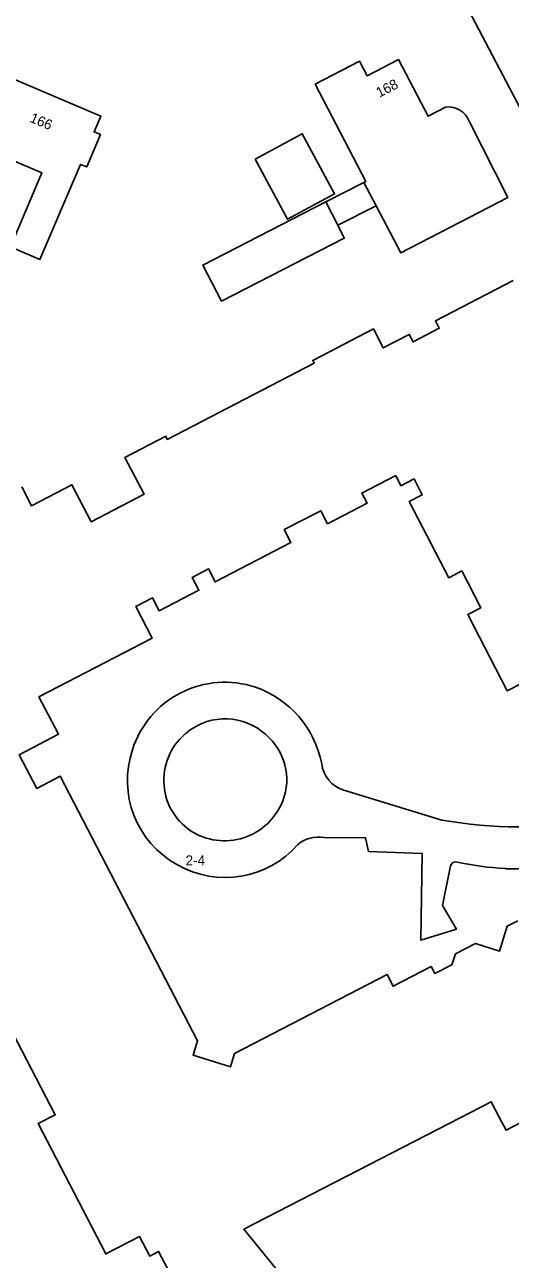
# Model space of a CAD drawing. Extents: x 162073 to 163043, y 381818 to 382561.
# Drawn here: x 162567.8 to 162616.1, y 382336.5 to 382459.4 of the extents above; entities that cross this region are included whole.
import ezdxf

# ---------------------------------------------------------------- set-up
doc = ezdxf.new("R2010")
doc.units = 0
for name, color, linetype in [('IMGEO_Erf', 7, 'Continuous'), ('IMGEO_Pand', 7, 'Continuous'), ('IMGEO_Pand_nummerreeks', 7, 'Continuous'), ('IMGEO_Rijbaan_lokaal_open', 7, 'Continuous')]:
    doc.layers.add(name, color=color, linetype=linetype)

msp = doc.modelspace()

# ---------------------------------------------------------------- linework, layer by layer
at = {"layer": 'IMGEO_Erf'}
for points in [[(162648.23, 382391.42), (162634.89, 382417.2), (162620.47, 382444.67), (162611.28, 382462.18)], [(162605.24, 382436.7), (162602.77, 382441.39), (162598.95, 382439.45), (162599.6, 382438.16), (162587.38, 382431.9), (162585.53, 382435.49), (162597.76, 382441.78), (162601.55, 382443.69), (162601.74, 382443.79), (162596.7, 382453.5), (162601.1, 382455.78), (162601.86, 382454.32), (162604.99, 382455.94), (162607.93, 382450.29), (162609.68, 382451.2)], [(162612.02, 382449.8), (162615.89, 382442.22), (162605.24, 382436.7)], [(162567.49, 382413.4), (162568.46, 382411.53), (162572.48, 382413.62), (162574.39, 382409.94), (162579.67, 382412.68), (162577.77, 382416.34), (162581.82, 382418.45), (162581.98, 382418.13), (162596.6, 382425.72), (162596.46, 382425.99), (162598.06, 382426.83), (162602.49, 382429.13), (162603.48, 382427.24), (162606.06, 382428.58), (162606.45, 382427.84), (162609.05, 382429.19), (162608.66, 382429.93), (162616.42, 382433.96)], [(162617.11, 382393.79), (162615.82, 382393.12), (162611.89, 382400.71), (162613.19, 382401.38), (162611.29, 382405.04), (162609.99, 382404.36), (162606.06, 382411.95), (162607.35, 382412.62), (162606.54, 382414.2), (162605.23, 382413.52), (162604.71, 382414.54), (162601.34, 382412.8), (162601.87, 382411.78), (162597.93, 382409.75), (162597.26, 382411.04), (162593.62, 382409.16), (162594.29, 382407.86), (162586.75, 382403.96), (162586.09, 382405.25), (162584.46, 382404.4), (162585.12, 382403.12), (162581.17, 382401.08), (162580.51, 382402.36), (162578.86, 382401.51), (162580.49, 382398.37), (162569.21, 382392.51), (162571.14, 382388.79), (162567.24, 382386.76), (162568.98, 382383.4), (162571.31, 382384.61), (162584.99, 382358.27), (162584.54, 382356.87), (162588.26, 382355.69), (162588.67, 382357.01), (162603.86, 382364.89), (162604.47, 382363.71), (162608.24, 382365.67), (162608.62, 382364.98), (162610.31, 382365.85), (162610.68, 382366.93), (162612.67, 382367.96), (162615.05, 382367.21), (162615.81, 382369.68), (162616.88, 382370.24)], [(162599.55, 382383.23), (162609.29, 382380.24)], [(162610.17, 382375.71), (162609.36, 382371.75), (162610.75, 382369.41), (162607.2, 382368.31), (162607.36, 382376.91), (162602.01, 382377.11), (162601.72, 382378.5), (162597.58, 382378.52)], [(162582.07, 382335.5), (162581.12, 382337.33), (162580.23, 382336.86), (162579.21, 382338.82), (162575.86, 382337.08), (162569.14, 382350.04), (162570.82, 382350.91), (162559.05, 382373.59)], [(162627.79, 382367.69), (162626.69, 382367.11), (162627.27, 382366.04), (162623.22, 382353.28), (162618.77, 382350.97), (162615.71, 382349.38), (162615.06, 382350.62), (162614.23, 382352.22), (162611.12, 382350.62), (162589.59, 382339.53), (162611.46, 382312.68), (162612.67, 382311.2), (162618.88, 382314.39), (162618.29, 382315.57), (162618.57, 382315.71), (162618.72, 382315.43), (162635.6, 382324.11)]]:
    msp.add_lwpolyline(points, dxfattribs=at)
for points in [[(162574.7, 382448.74), (162575.33, 382448.47), (162573.96, 382445.25), (162573.33, 382445.51), (162569.31, 382436.04), (162566.37, 382437.29), (162569.5, 382444.65), (162563.08, 382447.37), (162556.67, 382450.09), (162553.55, 382442.72), (162550.6, 382443.97), (162554.7, 382453.64), (162556.65, 382458.24), (162566.01, 382454.27), (162575.37, 382450.3)], [(162590.72, 382446.04), (162595.42, 382448.56), (162598.63, 382442.57), (162593.94, 382440.05)]]:
    msp.add_lwpolyline(points, close=True, dxfattribs=at)
for centre, radius, start, end in [((162609.98, 382449.04), 2.18, 20.4604, 97.972), ((162587.7, 382384.32), 9.65, 71.5619, 162.4034), ((162587.45, 382383.95), 10.08, 10.9461, 70.8873), ((162587.73, 382384.33), 6, 47.6619, 128.0131), ((162587.69, 382384.21), 6.06, 127.0261, 235.9029), ((162588.04, 382384.28), 5.83, 338.8097, 50.1498), ((162587.55, 382384.18), 9.54, 161.3358, 241.0949), ((162600.41, 382386.19), 3.08, 186.1264, 253.6945), ((162617.2, 382426.08), 46.51, 260.2078, 297.5867), ((162587.67, 382384.4), 6.21, 237.0021, 338.9856), ((162587.75, 382384.15), 9.61, 239.9538, 318.9447), ((162597.02, 382375.41), 3.16, 79.7797, 129.9923), ((162610.71, 382375.52), 0.573, 90.4987, 161.0596), ((162617.1, 382404.55), 29.16, 257.3311, 267.1127), ((162616.24, 382413.5), 38.09, 269.0873, 276.7222)]:
    msp.add_arc(centre, radius, start, end, dxfattribs=at)
at = {"layer": 'IMGEO_Pand'}
for points in [[(162609.68, 382451.2), (162607.93, 382450.29), (162604.99, 382455.94), (162601.86, 382454.32), (162601.1, 382455.78), (162596.7, 382453.5), (162601.74, 382443.79), (162601.55, 382443.69), (162602.77, 382441.39), (162605.24, 382436.7), (162615.89, 382442.22), (162612.02, 382449.8)], [(162616.42, 382433.96), (162608.66, 382429.93), (162609.05, 382429.19), (162606.45, 382427.84), (162606.06, 382428.58), (162603.48, 382427.24), (162602.49, 382429.13), (162598.06, 382426.83), (162596.46, 382425.99), (162596.6, 382425.72), (162581.98, 382418.13), (162581.82, 382418.45), (162577.77, 382416.34), (162579.67, 382412.68), (162574.39, 382409.94), (162572.48, 382413.62), (162568.46, 382411.53), (162567.49, 382413.4)], [(162616.88, 382370.24), (162615.81, 382369.68), (162615.05, 382367.21), (162612.67, 382367.96), (162610.68, 382366.93), (162610.31, 382365.85), (162608.62, 382364.98), (162608.24, 382365.67), (162604.47, 382363.71), (162603.86, 382364.89), (162588.67, 382357.01), (162588.26, 382355.69), (162584.54, 382356.87), (162584.99, 382358.27), (162571.31, 382384.61), (162568.98, 382383.4), (162567.24, 382386.76), (162571.14, 382388.79), (162569.21, 382392.51), (162580.49, 382398.37), (162578.86, 382401.51), (162580.51, 382402.36), (162581.17, 382401.08), (162585.12, 382403.12), (162584.46, 382404.4), (162586.09, 382405.25), (162586.75, 382403.96), (162594.29, 382407.86), (162593.62, 382409.16), (162597.26, 382411.04), (162597.93, 382409.75), (162601.87, 382411.78), (162601.34, 382412.8), (162604.71, 382414.54), (162605.23, 382413.52), (162606.54, 382414.2), (162607.35, 382412.62), (162606.06, 382411.95), (162609.99, 382404.36), (162611.29, 382405.04), (162613.19, 382401.38), (162611.89, 382400.71), (162615.82, 382393.12), (162617.11, 382393.79)], [(162559.05, 382373.59), (162570.82, 382350.91), (162569.14, 382350.04), (162575.86, 382337.08), (162579.21, 382338.82), (162580.23, 382336.86), (162581.12, 382337.33), (162582.07, 382335.5)], [(162611.46, 382312.68), (162589.59, 382339.53), (162611.12, 382350.62), (162614.23, 382352.22), (162615.06, 382350.62), (162615.71, 382349.38), (162618.77, 382350.97), (162623.22, 382353.28), (162627.27, 382366.04)]]:
    msp.add_lwpolyline(points, dxfattribs=at)
for points in [[(162563.08, 382447.37), (162569.5, 382444.65), (162566.37, 382437.29), (162569.31, 382436.04), (162573.33, 382445.51), (162573.96, 382445.25), (162575.33, 382448.47), (162574.7, 382448.74), (162575.37, 382450.3), (162566.01, 382454.27)], [(162590.72, 382446.04), (162593.94, 382440.05), (162598.63, 382442.57), (162595.42, 382448.56)], [(162601.55, 382443.69), (162597.76, 382441.78), (162598.95, 382439.45), (162602.77, 382441.39)], [(162598.95, 382439.45), (162597.76, 382441.78), (162585.53, 382435.49), (162587.38, 382431.9), (162599.6, 382438.16)]]:
    msp.add_lwpolyline(points, close=True, dxfattribs=at)
msp.add_arc((162609.98, 382449.04), 2.18, 20.4604, 97.972, dxfattribs=at)
at = {"layer": 'IMGEO_Rijbaan_lokaal_open'}
for points in [[(162611.28, 382462.18), (162620.47, 382444.67), (162634.89, 382417.2), (162648.23, 382391.42)], [(162609.29, 382380.24), (162599.55, 382383.23)], [(162597.58, 382378.52), (162601.72, 382378.5), (162602.01, 382377.11), (162607.36, 382376.91), (162607.2, 382368.31), (162610.75, 382369.41), (162609.36, 382371.75), (162610.17, 382375.71)]]:
    msp.add_lwpolyline(points, dxfattribs=at)
for centre, radius, start, end in [((162587.7, 382384.32), 9.65, 71.5619, 162.4034), ((162587.45, 382383.95), 10.08, 10.9461, 70.8873), ((162587.73, 382384.33), 6, 47.6619, 128.0131), ((162587.69, 382384.21), 6.06, 127.0261, 235.9029), ((162588.04, 382384.28), 5.83, 338.8097, 50.1498), ((162587.55, 382384.18), 9.54, 161.3358, 241.0949), ((162600.41, 382386.19), 3.08, 186.1264, 253.6945), ((162617.2, 382426.08), 46.51, 260.2078, 297.5867), ((162587.67, 382384.4), 6.21, 237.0021, 338.9856), ((162587.75, 382384.15), 9.61, 239.9538, 318.9447), ((162597.02, 382375.41), 3.16, 79.7797, 129.9923), ((162610.71, 382375.52), 0.573, 90.4987, 161.0596), ((162617.1, 382404.55), 29.16, 257.3311, 267.1127), ((162616.24, 382413.5), 38.09, 269.0873, 276.7222)]:
    msp.add_arc(centre, radius, start, end, dxfattribs=at)

# ---------------------------------------------------------------- texts
at = {"layer": 'IMGEO_Pand_nummerreeks'}
for s, rotation, p in [('168', 27.227, (162603.08, 382452.14)), ('166', 337.0231, (162568.22, 382449.77))]:
    msp.add_text(s, height=1, rotation=rotation, dxfattribs=at).set_placement(p)
msp.add_text('2-4', height=1, dxfattribs=at).set_placement((162583.8, 382375.74))

doc.saveas('drawing.dxf')
